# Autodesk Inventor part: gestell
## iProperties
Created: 2007-11
Part Number: gestell
Document SubType Name: Modeling
Designer: martin
Manufacturer: Standard
Standards Organization: Custom
Author: martin
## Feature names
1. Extrusion2
2. Extrusion3
3. Extrusion4
